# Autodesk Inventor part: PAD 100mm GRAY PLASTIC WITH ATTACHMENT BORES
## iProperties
Created: 2007-03
Part Number: PAD 100mm GRAY PLASTIC WITH ATTACHMENT BORES
Document SubType Name: Modeling
Designer: Andy Moles
Material: ABS Plastic
Density: 1.06 g/cm^3
Author: Andy Moles
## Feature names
1. Revolution1
2. Extrusion1
3. Extrusion2
4. Extrusion3
5. Fillet1
6. Extrusion4
